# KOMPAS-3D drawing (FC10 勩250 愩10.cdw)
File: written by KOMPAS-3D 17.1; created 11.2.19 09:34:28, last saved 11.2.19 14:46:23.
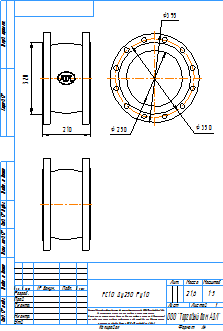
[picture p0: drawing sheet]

Sheet 1: A4, portrait

Title block, sheet 1: name: FC10 Ду250 Ру10; mass: 21,6; sheets: 1; sheet format: A4; stored path: \\adlc.lan\data\АДЛ_ПКД\3D-модели\ADL production\Гибкие вставки серии FC\FC10\KOMPAS 2D\FC10 Ду250 Ру10.cdw

Views: Вид 1
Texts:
  kka
  adl
  Рама для чертежей
  Лит-Масса-Масштаб
  Материал-Предприятие
  Масштаб
  Изм.
  Лист
  № докум.
  Подп.
  Дата
  Лит.
  Разраб.
  Пров.
  Т.контр.
  Листов
  Внимание! Данный продукт является объектом авторского права ООО «Торговый Дом АДЛ».
  Запрещается изменение, копирование, распространение
  (в том числе путем копирования на другие сайты и ресурсы в Интернете)
  или любое иное использование информации и объектов без предварительного
  согласия правообладателя (ООО «Торговый Дом АДЛ»).
  Н.контр.
  Утв.
  ООО "Торговый дом АДЛ"
  Изменение
  Номер документа
  Подпись
  Обозначение документа
  Наименование изделия
  Масса изделия по ГОСТ 2.109-73
  Порядковый номер листа
  Общее количество листов в документе
  Характер работы, выполненной лицом, подписавшим документ
  Наименование или индекс предприятия, выпускающего документ
  Инв. № подл.
  Подп. и дата
  Взам. инв. №
  Инв. № дубл.
  Инвентарный номер подлинника по ГОСТ 2.501-68
  Подпись принявшего подлинник в отдел технической документации
  Инвентарный номер подлинника, взамен которого выпущен данный подлинник
  Инвентарный номер дубликата по ГОСТ 2.502-68
  Подпись принявшего дубликат в отдел технической документации
  Справ. №
  Перв. примен.
  Обозначение документа, взамен или на основании которого выпущен данный документ
  Обозначение документа, в котором впервые записан данный документ
  Подпись лица, копировавшего чертеж
  Обозначение формата листа
  !Рама для чертежа
Dimensions and other numbers on the sheet: 210; 320; 250; 350; 395; 1:5; 1; 21,6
